// Mitsubishi GX Works2 project: 红绿灯测试(王：步进指令)   PLC: FX3U/FX3UC

PROGRAM MAIN
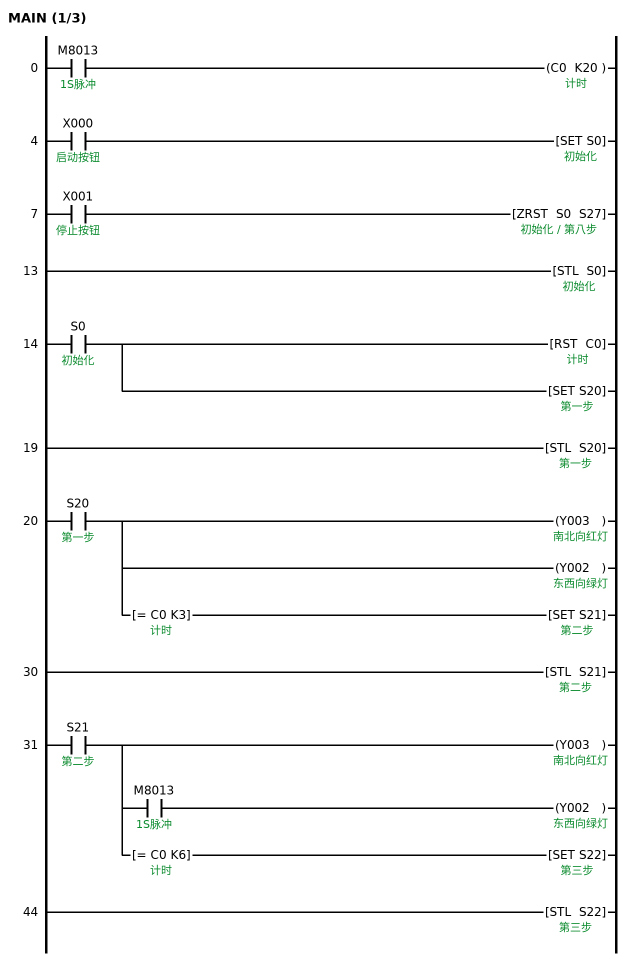
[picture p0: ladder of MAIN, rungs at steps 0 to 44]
0     LD      M8013  ; 1S脉冲
      OUT     C0 K20  ; 计时
4     LD      X000  ; 启动按钮
      SET     S0  ; 初始化
7     LD      X001  ; 停止按钮
      ZRST    S0 S27  ; 第八步
13    STL     S0
14    LD      S0  ; 初始化
      RST     C0  ; 计时
      SET     S20  ; 第一步
19    STL     S20
20    LD      S20  ; 第一步
      OUT     Y003  ; 南北向红灯
      OUT     Y002  ; 东西向绿灯
      AND=    C0 K3  ; 计时
      SET     S21  ; 第二步
30    STL     S21
31    LD      S21  ; 第二步
      OUT     Y003  ; 南北向红灯
      MPS
      AND     M8013  ; 1S脉冲
      OUT     Y002  ; 东西向绿灯
        [note] 绿灯闪烁3秒
      MPP
      AND=    C0 K6  ; 计时
      SET     S22  ; 第三步
44    STL     S22
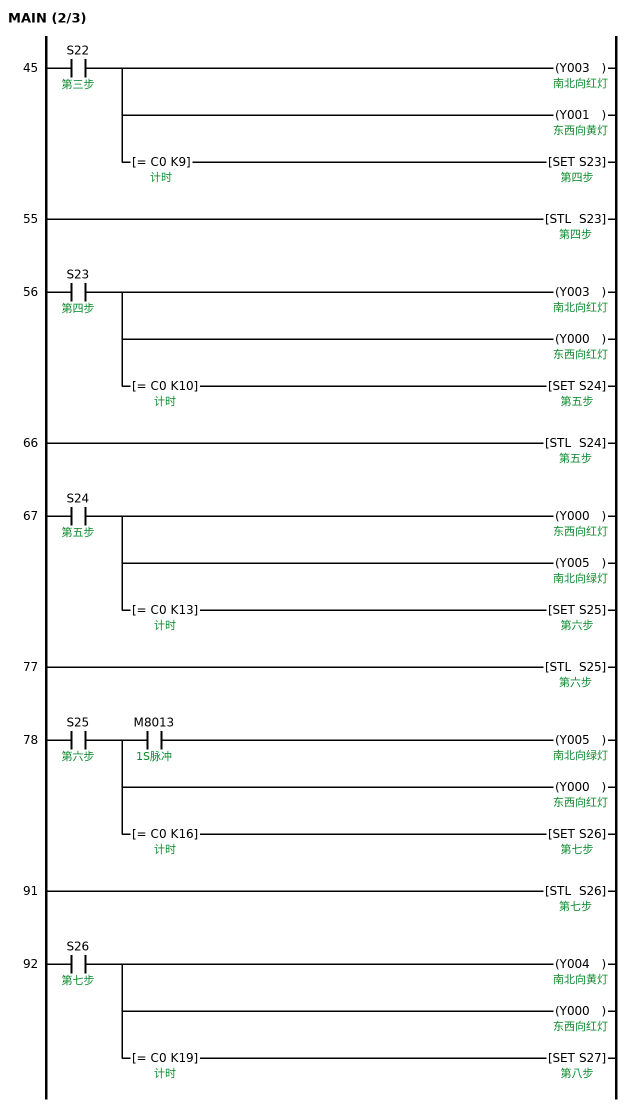
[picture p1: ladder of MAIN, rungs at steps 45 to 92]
45    LD      S22  ; 第三步
      OUT     Y003  ; 南北向红灯
      OUT     Y001  ; 东西向黄灯
      AND=    C0 K9  ; 计时
      SET     S23  ; 第四步
55    STL     S23
56    LD      S23  ; 第四步
      OUT     Y003  ; 南北向红灯
      OUT     Y000  ; 东西向红灯
      AND=    C0 K10  ; 计时
      SET     S24  ; 第五步
66    STL     S24
67    LD      S24  ; 第五步
      OUT     Y000  ; 东西向红灯
      OUT     Y005  ; 南北向绿灯
      AND=    C0 K13  ; 计时
      SET     S25  ; 第六步
77    STL     S25
78    LD      S25  ; 第六步
      MPS
      AND     M8013  ; 1S脉冲
      OUT     Y005  ; 南北向绿灯
      MPP
      OUT     Y000  ; 东西向红灯
      AND=    C0 K16  ; 计时
      SET     S26  ; 第七步
91    STL     S26
92    LD      S26  ; 第七步
      OUT     Y004  ; 南北向黄灯
      OUT     Y000  ; 东西向红灯
      AND=    C0 K19  ; 计时
      SET     S27  ; 第八步
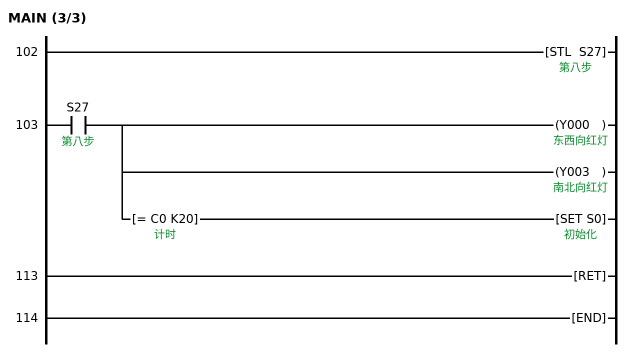
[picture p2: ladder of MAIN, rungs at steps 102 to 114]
102   STL     S27
103   LD      S27  ; 第八步
      OUT     Y000  ; 东西向红灯
      OUT     Y003  ; 南北向红灯
      AND=    C0 K20  ; 计时
      SET     S0  ; 初始化
        [note] 返回初始化
113   RET
114   END
END_PROGRAM
